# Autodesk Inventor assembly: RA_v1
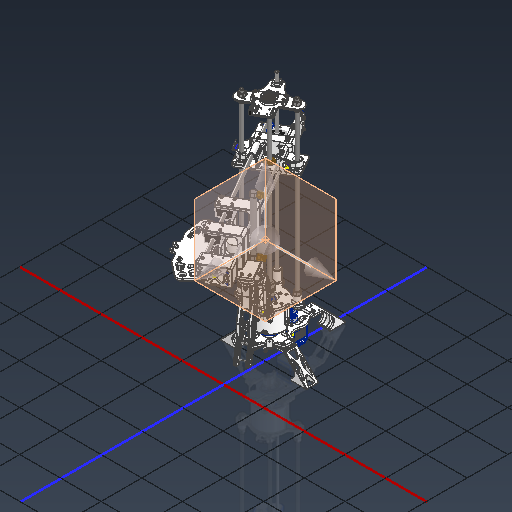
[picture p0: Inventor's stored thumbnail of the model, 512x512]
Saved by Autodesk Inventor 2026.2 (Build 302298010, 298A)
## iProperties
Created: 2026-04
Part Number: RA_v1
Document SubType Name: Assembly
Designer: work
Mass: 3600.07 g
Surface Area: 4552.63 cm^2
Volume: 1032.21 cm^3
Author: work
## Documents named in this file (45)
- C:\Users\khw\Desktop\ARD_v1\ARD_hardware\RA_Project\RA_v1.iam
- C:\Users\khw\Desktop\ARD_v1\ARD_hardware\RA_Project\48 Timing Belt Pulli.ipt
- C:\Users\khw\Desktop\ARD_v1\ARD_hardware\RA_Project\Y-axis - pulley support plate.ipt
- C:\Users\khw\Desktop\ARD_v1\ARD_hardware\RA_Project\Y-axis rotation plate.ipt
- C:\Users\khw\Desktop\ARD_v1\ARD_hardware\RA_Project\NEMA17.ipt
- C:\Users\khw\Desktop\ARD_v1\ARD_hardware\RA_Project\VL53L0X.ipt
- C:\Users\khw\Desktop\ARD_v1\ARD_hardware\RA_Project\X-axis fixing plate.ipt
- C:\Users\khw\Desktop\ARD_v1\ARD_hardware\RA_Project\JIS B 1521 - 625 5x16x5x1.73.ipt
- C:\Users\khw\Desktop\ARD_v1\ARD_hardware\RA_Project\5pi pin.ipt
- C:\Users\khw\Desktop\ARD_v1\ARD_hardware\RA_Project\X-axis disc support.ipt
- C:\Users\khw\Desktop\ARD_v1\ARD_hardware\RA_Project\T8linear shaft.ipt
- C:\Users\khw\Desktop\ARD_v1\ARD_hardware\RA_Project\T8Screws.ipt
- C:\Users\khw\Desktop\ARD_v1\ARD_hardware\RA_Project\8T_ScrewShaft.ipt
- C:\Users\khw\Desktop\ARD_v1\ARD_hardware\RA_Project\T8_BellowsCoulping.ipt
- C:\Users\khw\Desktop\ARD_v1\ARD_hardware\RA_Project\Y-axis End Leveler Mount.ipt
- C:\Users\khw\Desktop\ARD_v1\ARD_hardware\RA_Project\Y-axis end.ipt
- C:\Users\khw\Desktop\ARD_v1\ARD_hardware\RA_Project\Y-axis fixture.ipt
- C:\Users\khw\Desktop\ARD_v1\ARD_hardware\RA_Project\Y-axis Support fixing.ipt
- C:\Users\khw\Desktop\ARD_v1\ARD_hardware\RA_Project\T8_LeadNut.ipt
- C:\Users\khw\Desktop\ARD_v1\ARD_hardware\RA_Project\LeadWay.ipt
- C:\Users\khw\Desktop\ARD_v1\ARD_hardware\RA_Project\LimitedSwitch.ipt
- C:\Users\khw\Desktop\ARD_v1\ARD_hardware\RA_Project\24 Timing Belt Pulli.ipt
- C:\Users\khw\Desktop\ARD_v1\ARD_hardware\RA_Project\Al shaft 5pi-500mm.ipt
- C:\Users\khw\Desktop\ARD_v1\ARD_hardware\RA_Project\z-axis bearing puller support.ipt
- C:\Users\khw\Desktop\ARD_v1\ARD_hardware\RA_Project\end of the z-axis.ipt
- C:\Users\khw\Desktop\ARD_v1\ARD_hardware\RA_Project\KS B 1003 - M 3 x 16.ipt
- C:\Users\khw\Desktop\ARD_v1\ARD_hardware\RA_Project\KS B 1003 - M 2 x 10.ipt
- C:\Users\khw\Desktop\ARD_v1\ARD_hardware\RA_Project\JIS B 1521 - 623 3x10x4x0.630.ipt
- C:\Users\khw\Documents\Inventor\Content Center Files\R2026\ko-KR\KS B 1003\KS B 1003 - M 3 x 5.ipt
- C:\Users\khw\Desktop\ARD_v1\ARD_hardware\RA_Project\KS B 1003 - M 3 x 12.ipt
- C:\Users\khw\Documents\Inventor\Content Center Files\R2026\ko-KR\KS B 1003\KS B 1003 - M 2.5 x 4.ipt
- C:\Users\khw\Desktop\ARD_v1\ARD_hardware\RA_Project\KS B 1028 - M2.5x5(1).ipt
- C:\Users\khw\Desktop\ARD_v1\ARD_hardware\RA_Project\KS B 1028 - M3x5(1).ipt
- C:\Users\khw\Desktop\ARD_v1\ARD_hardware\RA_Project\KS B 1012 - C M8C.ipt
- C:\Users\khw\Desktop\ARD_v1\ARD_hardware\RA_Project\KS B 1003 - M 4 x 16.ipt
- C:\Users\khw\Desktop\ARD_v1\ARD_hardware\RA_Project\MPU-6050.ipt
- C:\Users\khw\Desktop\ARD_v1\ARD_hardware\RA_Project\Z-axis mover parts\Z-axis mover 2.ipt
- C:\Users\khw\Desktop\ARD_v1\ARD_hardware\RA_Project\Z-axis mover parts\Z-axis mover 1.ipt
- C:\Users\khw\Desktop\ARD_v1\ARD_hardware\RA_Project\JIS B 1521 - 608 8x22x7x3.3.ipt
- C:\Users\khw\Desktop\ARD_v1\ARD_hardware\RA_Project\KS B 1003 - M 1.6 x 2.5.ipt
- C:\Users\khw\Desktop\ARD_v1\ARD_hardware\RA_Project\Head\head stator.ipt
- C:\Users\khw\Desktop\ARD_v1\ARD_hardware\RA_Project\Head\GT2 Timing Belt Fixation.ipt
- C:\Users\khw\Desktop\ARD_v1\ARD_hardware\RA_Project\Head\Head connection and motor stator.ipt
- C:\Users\khw\Desktop\ARD_v1\ARD_hardware\RA_Project\28BJY-48.ipt
- C:\Users\khw\Desktop\ARD_v1\ARD_hardware\PneumaticGripper_v1\PneumaticGripper_v1.1.iam
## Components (166 placed, 44 different names)
1. 48 Timing Belt Pulli:1 — 플러쉬:1
2. Y-axis - pulley support plate:1
3. Y-axis rotation plate:1
4. NEMA17:1 — 각도:2
5. VL53L0X:1
6. X-axis fixing plate:1
7. NEMA17:2 — 플러쉬:4, 각도:9
8. 5pi pin:1 — 플러쉬:1
9. X-axis disc support:1
10. X-axis disc support:3
11. X-axis disc support:4
12. T8linear shaft:1
13. T8Screws:1 — 플러쉬:2
14. T8Screws:2 — 플러쉬:3
15. 8T_ScrewShaft:1 — 플러쉬:13
16. T8_BellowsCoulping:1
17. Y-axis End Leveler Mount:1 — 각도:3
18. Y-axis end:1
19. Y-axis fixture:1
20. Y-axis Support fixing:1
21. T8_LeadNut:1
22. LeadWay:1
23. LimitedSwitch:1 — 각도:4
24. 24 Timing Belt Pulli:1 — 플러쉬:4, 강체:2, 강체:3
25. T8linear shaft:2 — 플러쉬:11
26. NEMA17:3 — 플러쉬:6, 각도:7, 각도:9
27. 24 Timing Belt Pulli:2 — 플러쉬:6, 강체:4, 강체:5
28. Z-axis mover 2:1
29. Z-axis mover 1:1
30. MPU-6050:3
31. head stator:1
32. GT2 Timing Belt Fixation:1
33. GT2 Timing Belt Fixation:2
34. LeadWay:2
35. head stator:2
36. GT2 Timing Belt Fixation:3
37. GT2 Timing Belt Fixation:4
38. LeadWay:3
39. Head connection and motor stator:1
40. 28BJY-48:1
41. KS B 1003 - 미터 M 3 x 5:80
42. KS B 1003 - 미터 M 3 x 5:81
43. KS B 1003 - 미터 M 3 x 5:82
44. KS B 1003 - 미터 M 3 x 5:83
45. KS B 1003 - 미터 M 3 x 5:84
46. KS B 1003 - 미터 M 3 x 5:85
47. KS B 1003 - 미터 M 3 x 5:86
48. KS B 1003 - 미터 M 3 x 5:87
49. KS B 1003 - 미터 M 3 x 5:88
50. KS B 1003 - 미터 M 3 x 5:89
51. KS B 1003 - 미터 M 3 x 5:90
52. KS B 1003 - 미터 M 3 x 5:91
53. KS B 1003 - 미터 M 3 x 5:92
54. KS B 1003 - 미터 M 3 x 5:93
55. KS B 1003 - 미터 M 3 x 5:94
56. KS B 1003 - 미터 M 3 x 5:95
57. KS B 1003 - 미터 M 3 x 5:96
58. KS B 1003 - 미터 M 3 x 5:97
59. PneumaticGripper_v1.1:1 [sub-assembly] — 각도:10
60. JIS B 1521 - 625 5x16x5x1.73:1
61. KS B 1003 - 미터 M 3 x 5:76
62. KS B 1003 - 미터 M 3 x 5:77
63. KS B 1003 - 미터 M 3 x 5:78
64. KS B 1003 - 미터 M 3 x 5:79
65. KS B 1003 - 미터 M 3 x 5:72
66. KS B 1003 - 미터 M 3 x 5:73
67. KS B 1003 - 미터 M 3 x 5:74
68. KS B 1003 - 미터 M 3 x 5:75
69. KS B 1003 - 미터 M 3 x 5:68
70. KS B 1003 - 미터 M 3 x 5:69
71. KS B 1003 - 미터 M 3 x 5:70
72. KS B 1003 - 미터 M 3 x 5:71
73. KS B 1003 - 미터 M 3 x 5:64
74. KS B 1003 - 미터 M 3 x 5:65
75. KS B 1003 - 미터 M 3 x 5:66
76. KS B 1003 - 미터 M 3 x 5:67
77. JIS B 1521 - 608 8x22x7x3.3:1
78. KS B 1003 - 미터 M 3 x 5:44
79. KS B 1003 - 미터 M 3 x 5:45
80. KS B 1003 - 미터 M 3 x 5:46
81. KS B 1003 - 미터 M 3 x 5:47
82. KS B 1003 - 미터 M 3 x 5:48
83. KS B 1003 - 미터 M 3 x 5:49
84. KS B 1003 - 미터 M 3 x 5:50
85. KS B 1003 - 미터 M 3 x 5:51
86. KS B 1003 - 미터 M 3 x 5:52
87. KS B 1003 - 미터 M 3 x 5:53
88. KS B 1003 - 미터 M 3 x 5:54
89. KS B 1003 - 미터 M 3 x 5:55
90. KS B 1003 - 미터 M 3 x 5:56
91. KS B 1003 - 미터 M 3 x 5:57
92. KS B 1003 - 미터 M 3 x 5:58
93. KS B 1003 - 미터 M 3 x 5:59
94. KS B 1003 - 미터 M 3 x 5:60
95. KS B 1003 - 미터 M 3 x 5:61
96. KS B 1003 - 미터 M 3 x 5:62
97. KS B 1003 - 미터 M 3 x 5:63
98. KS B 1003 - 미터 M 2.5 x 4:3
99. KS B 1003 - 미터 M 2.5 x 4:4
100. KS B 1003 - 미터 M 2.5 x 4:5
101. KS B 1003 - 미터 M 2.5 x 4:6
102. KS B 1003 - M 1.6 x 2.5:1
103. KS B 1003 - M 1.6 x 2.5:2
104. KS B 1003 - M 1.6 x 2.5:3
105. KS B 1003 - M 1.6 x 2.5:4
106. Al shaft 5pi-500mm:1 — 플러쉬:10, 플러쉬:12
107. Al shaft 5pi-500mm:2 — 플러쉬:9
108. z-axis bearing puller support:1
109. end of the z-axis:1 — 플러쉬:9, 각도:6, 플러쉬:10, 플러쉬:11
110. KS B 1003 - M 3 x 16:1
111. KS B 1003 - M 2 x 10:1
112. KS B 1003 - M 2 x 10:2
113. JIS B 1521 - 623 3x10x4x0.630:1
114. JIS B 1521 - 623 3x10x4x0.630:2
115. VL53L0X:2 — 각도:8
116. LimitedSwitch:2 — 각도:6
117. KS B 1003 - M 3 x 12:1
118. KS B 1003 - 미터 M 3 x 5:1
119. KS B 1003 - 미터 M 3 x 5:2
120. KS B 1003 - 미터 M 3 x 5:3
121. KS B 1003 - 미터 M 3 x 5:4
122. KS B 1003 - 미터 M 3 x 5:5
123. KS B 1003 - 미터 M 3 x 5:6
124. KS B 1003 - 미터 M 3 x 5:7
125. KS B 1003 - 미터 M 3 x 5:8
126. KS B 1003 - 미터 M 3 x 5:9
127. KS B 1003 - 미터 M 2.5 x 4:1
128. KS B 1003 - 미터 M 2.5 x 4:2
129. KS B 1003 - 미터 M 3 x 5:10
130. KS B 1003 - 미터 M 3 x 5:11
131. KS B 1003 - 미터 M 3 x 5:12
132. KS B 1003 - 미터 M 3 x 5:13
133. KS B 1003 - 미터 M 3 x 5:14
134. KS B 1003 - 미터 M 3 x 5:15
135. KS B 1003 - 미터 M 3 x 5:16
136. KS B 1003 - 미터 M 3 x 5:17
137. KS B 1003 - 미터 M 3 x 5:18
138. KS B 1003 - 미터 M 3 x 5:19
139. KS B 1003 - 미터 M 3 x 5:20
140. KS B 1003 - 미터 M 3 x 5:21
141. KS B 1003 - 미터 M 3 x 5:36
142. KS B 1003 - 미터 M 3 x 5:37
143. KS B 1003 - 미터 M 3 x 5:38
144. KS B 1003 - 미터 M 3 x 5:39
145. KS B 1028 - M2.5x5(1):4 — 강체:2
146. KS B 1028 - M2.5x5(1):5 — 강체:3
147. KS B 1028 - M2.5x5(1):6 — 강체:4
148. KS B 1028 - M2.5x5(1):7 — 강체:5
149. KS B 1028 - M3x5(1):1 — 강체:7
150. KS B 1028 - M3x5(1):2 — 강체:6
151. KS B 1003 - 미터 M 3 x 5:40
152. KS B 1012 - C M8C:1
153. KS B 1012 - C M8C:2
154. KS B 1012 - C M8C:3
155. KS B 1012 - C M8C:4
156. KS B 1012 - C M8C:5
157. KS B 1012 - C M8C:6
158. KS B 1012 - C M8C:7
159. KS B 1012 - C M8C:8
160. KS B 1003 - 미터 M 3 x 5:41
161. KS B 1003 - M 4 x 16:1
162. KS B 1003 - M 4 x 16:2
163. KS B 1003 - M 4 x 16:3
164. KS B 1003 - M 4 x 16:4
165. KS B 1003 - 미터 M 3 x 5:42
166. KS B 1003 - 미터 M 3 x 5:43
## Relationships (24: Flush 10, Angle 8, WeldJoint 6)
- 플러쉬:1 [Flush]: 48 Timing Belt Pulli:1 ↔ 5pi pin:1
- 플러쉬:2 [Flush]: T8Screws:1
- 플러쉬:3 [Flush]: T8Screws:2
- 각도:2 [Angle]: NEMA17:1
- 각도:3 [Angle]: Y-axis End Leveler Mount:1
- 각도:4 [Angle]: LimitedSwitch:1
- 플러쉬:4 [Flush]: NEMA17:2 ↔ 24 Timing Belt Pulli:1
- 플러쉬:6 [Flush]: NEMA17:3 ↔ 24 Timing Belt Pulli:2
- 플러쉬:9 [Flush]: Al shaft 5pi-500mm:2 ↔ end of the z-axis:1
- 각도:6 [Angle]: end of the z-axis:1 ↔ LimitedSwitch:2
- 강체:2 [WeldJoint]: 24 Timing Belt Pulli:1 ↔ KS B 1028 - M2.5x5(1):4
- 강체:3 [WeldJoint]: 24 Timing Belt Pulli:1 ↔ KS B 1028 - M2.5x5(1):5
- 강체:4 [WeldJoint]: 24 Timing Belt Pulli:2 ↔ KS B 1028 - M2.5x5(1):6
- 강체:5 [WeldJoint]: 24 Timing Belt Pulli:2 ↔ KS B 1028 - M2.5x5(1):7
- 강체:6 [WeldJoint]: KS B 1028 - M3x5(1):2
- 강체:7 [WeldJoint]: KS B 1028 - M3x5(1):1
- 각도:7 [Angle]: NEMA17:3
- 플러쉬:10 [Flush]: Al shaft 5pi-500mm:1 ↔ end of the z-axis:1
- 플러쉬:11 [Flush]: T8linear shaft:2 ↔ end of the z-axis:1
- 플러쉬:12 [Flush]: Al shaft 5pi-500mm:1
- 플러쉬:13 [Flush]: 8T_ScrewShaft:1
- 각도:8 [Angle]: VL53L0X:2
- 각도:9 [Angle]: NEMA17:2 ↔ NEMA17:3
- 각도:10 [Angle]: PneumaticGripper_v1.1:1
## Named parameters: d444_d411 = 0, d445_d412 = 0, d446_d413 = 0, d447_d414 = 0, d448_d415 = 0, d449_d416 = 0, d450_d417 = 0, d451_d418 = 0, d452_d419 = 0, d453_d420 = 0, d454_d421 = 0, d455_d422 = 0, d456_d423 = 0, d457_d424 = 0, d458_d425 = 0, d459_d426 = 0, d460_d427 = 0, d461_d428 = 0, d462_d429 = 0, d463_d430 = 0, d464_d431 = 0, d465_d432 = 0, d466_d433 = 0, d467_d434 = 0, d468_d435 = 0, d469_d436 = 0, d470_d437 = 0, d471_d438 = 0, d472_d439 = 0, d473_d440 = 0, d474_d441 = 0, d475_d442 = 0, d476_d443 = 0
